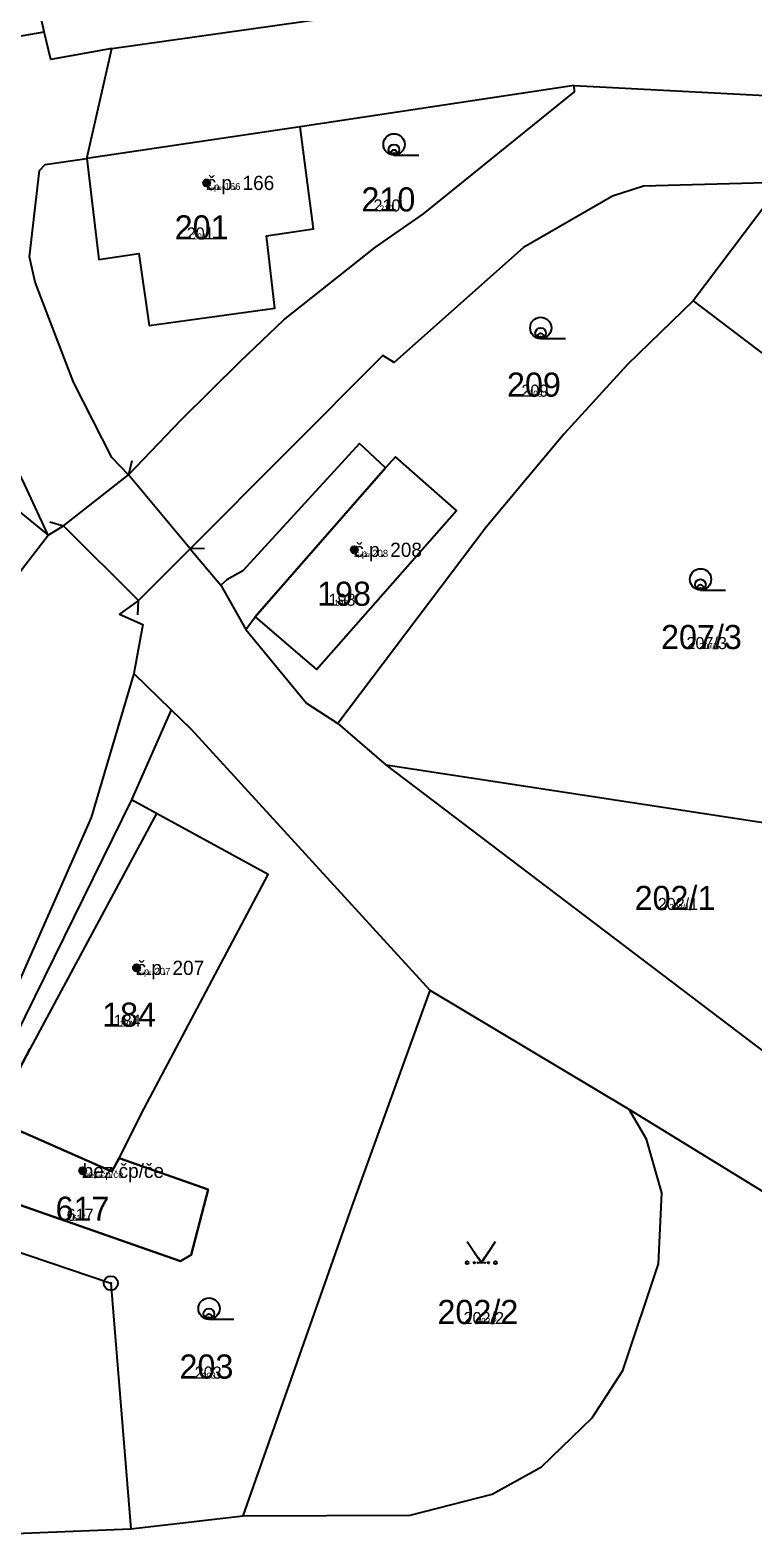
# Model space of a CAD drawing. Extents: x -744652 to -739090, y -980828 to -975855.
# Drawn here: x -742254.9 to -742204.1, y -978789.8 to -978683.6 of the extents above; entities that cross this region are included whole.
import ezdxf

# ---------------------------------------------------------------- set-up
doc = ezdxf.new("R2010")
doc.units = 0
for name, color, linetype in [('KAT_02_hranice parcel', 7, 'Continuous'), ('KAT_03_1000_st čísla parcelní', 7, 'Continuous'), ('KAT_03_1000_čísla parcelní', 7, 'Continuous'), ('KAT_03_1000_čísla popisná', 7, 'Continuous'), ('KAT_03_100_st čísla parcelní', 7, 'Continuous'), ('KAT_03_100_čísla parcelní', 7, 'Continuous'), ('KAT_03_100_čísla popisná', 7, 'Continuous'), ('KAT_03_250_st čísla parcelní', 7, 'Continuous'), ('KAT_03_250_čísla parcelní', 7, 'Continuous'), ('KAT_03_250_čísla popisná', 7, 'Continuous'), ('KAT_03_500_st čísla parcelní', 7, 'Continuous'), ('KAT_03_500_čísla parcelní', 7, 'Continuous'), ('KAT_03_500_čísla popisná', 7, 'Continuous'), ('KAT_04_vnitřní kresba', 7, 'Continuous'), ('KAT_05_1000_značky kultur', 7, 'Continuous'), ('KAT_05_100_značky kultur', 7, 'Continuous'), ('KAT_05_250_značky kultur', 7, 'Continuous'), ('KAT_05_500_značky kultur', 7, 'Continuous'), ('KAT_07_1000_značky budov', 7, 'Continuous'), ('KAT_07_100_značky budov', 7, 'Continuous'), ('KAT_07_500_značky budov', 7, 'Continuous'), ('KAT_11_značky bodu BP', 7, 'Continuous'), ('KAT_14_plocha_budovy', 7, 'Continuous')]:
    doc.layers.add(name, color=color, linetype=linetype)

msp = doc.modelspace()

# ---------------------------------------------------------------- linework, layer by layer
at = {"layer": 'KAT_02_hranice parcel'}
for p, q in [((-742253.92, -978683.75), (-742256.12, -978674.23)), ((-742249.16, -978684.92), (-742229.9, -978682.2)), ((-742250.94, -978692.66), (-742249.16, -978684.92)), ((-742216.65, -978687.54), (-742235.91, -978690.44)), ((-742235.91, -978690.44), (-742250.94, -978692.66)), ((-742243.66, -978720.15), (-742241.49, -978722.71)), ((-742241.49, -978722.71), (-742239.75, -978725.82)), ((-742245, -978731.48), (-742247.62, -978728.93)), ((-742245, -978731.48), (-742247.78, -978737.83)), ((-742233.28, -978732.45), (-742229.86, -978735.38)), ((-742229.86, -978735.38), (-742202.46, -978756.19)), ((-742200.11, -978739.93), (-742229.86, -978735.38)), ((-742247.78, -978737.83), (-742260.24, -978763.13)), ((-742212.78, -978759.62), (-742226.77, -978751.25)), ((-742198.03, -978768.69), (-742212.78, -978759.62)), ((-742247.84, -978789.14), (-742239.93, -978788.24))]:
    msp.add_line(p, q, dxfattribs=at)
for points in [[(-742295.99, -978688.82), (-742287.76, -978689.58), (-742287.82, -978690.14), (-742286.97, -978690.21), (-742286.81, -978689.69), (-742265.35, -978685.74), (-742253.92, -978683.75)], [(-742249.16, -978684.92), (-742253.45, -978685.69), (-742253.92, -978683.75)], [(-742248, -978714.93), (-742244.3, -978711.07), (-742240.12, -978706.95), (-742237.06, -978704.04), (-742230.63, -978698.92), (-742227.24, -978696.57), (-742216.61, -978687.98), (-742216.65, -978687.54)], [(-742216.65, -978687.54), (-742202.73, -978688.25), (-742196.45, -978690.11), (-742194.34, -978691.41), (-742192.8, -978692.35), (-742189.04, -978695.18), (-742173.16, -978709.75), (-742166.45, -978714.63), (-742161.92, -978717.51), (-742156.4, -978720.68), (-742110.16, -978740.68), (-742085.64, -978751.42), (-742066.41, -978761.84), (-742062.23, -978766.39), (-742061.65, -978767.53), (-742052.39, -978779.37), (-742045.8, -978788.93)], [(-742250.94, -978692.66), (-742250.09, -978699.79), (-742247.26, -978699.36), (-742246.54, -978704.43), (-742237.7, -978703.2), (-742238.28, -978698.11), (-742234.98, -978697.63), (-742235.91, -978690.44)], [(-742248, -978714.93), (-742249.18, -978713.71), (-742251.87, -978708.42), (-742254.57, -978701.37), (-742254.97, -978699.59), (-742254.26, -978693.51), (-742253.85, -978693.09), (-742250.94, -978692.66)], [(-742202.27, -978694.37), (-742211.76, -978694.63), (-742213.94, -978695.32), (-742220.2, -978698.93), (-742229.3, -978707.04), (-742230.11, -978706.53), (-742243.66, -978720.15)], [(-742202.27, -978694.37), (-742202.84, -978695.52), (-742208.28, -978702.7)], [(-742253.66, -978719.18), (-742255.46, -978715.29), (-742261.65, -978703.21), (-742265.29, -978698.76), (-742268.77, -978697.28), (-742274.49, -978696.87), (-742278.62, -978699.47)], [(-742208.28, -978702.7), (-742212.9, -978707.18), (-742217.35, -978712.05), (-742222.84, -978718.63), (-742233.28, -978732.45)], [(-742208.28, -978702.7), (-742201.85, -978707.57), (-742199.68, -978709.84)], [(-742279.4, -978730.44), (-742277.71, -978707.74), (-742276.98, -978703.66), (-742268.28, -978707.22), (-742253.66, -978719.18)], [(-742239.75, -978725.82), (-742239.09, -978724.94), (-742234.78, -978728.65), (-742224.92, -978717.45), (-742229.22, -978713.67), (-742229.91, -978714.46), (-742231.74, -978712.74), (-742239.95, -978721.7), (-742241.09, -978722.33), (-742241.49, -978722.71)], [(-742253.66, -978719.18), (-742252.57, -978718.53), (-742248, -978714.93)], [(-742262.83, -978733.44), (-742258.16, -978725), (-742253.66, -978719.18)], [(-742243.66, -978720.15), (-742247.3, -978723.8), (-742248.63, -978724.76), (-742246.99, -978725.49), (-742247.62, -978728.93)], [(-742239.75, -978725.82), (-742235.47, -978731.02), (-742233.28, -978732.45)], [(-742247.62, -978728.93), (-742250.63, -978739.07), (-742262.99, -978767.12)], [(-742226.77, -978751.25), (-742243.57, -978732.88), (-742245, -978731.48)], [(-742248.65, -978763.05), (-742246.89, -978759.56), (-742238.17, -978743.09), (-742246.03, -978738.79), (-742247.78, -978737.83)], [(-742239.93, -978788.24), (-742232.26, -978766.43), (-742226.77, -978751.25)], [(-742239.93, -978788.24), (-742228.19, -978788.19), (-742222.41, -978786.71), (-742218.94, -978784.79), (-742215.38, -978781.34), (-742213.21, -978778.01), (-742210.71, -978770.48), (-742210.48, -978765.5), (-742211.54, -978761.72), (-742212.78, -978759.62)], [(-742257.54, -978760.3), (-742249.17, -978764), (-742248.65, -978763.05)], [(-742248.65, -978763.05), (-742242.4, -978765.25), (-742243.58, -978769.85), (-742244.33, -978770.31), (-742259.91, -978764.86)], [(-742262.35, -978767.41), (-742269.82, -978775.08), (-742287.73, -978785.83), (-742275.64, -978787.82), (-742263.54, -978789.78), (-742247.84, -978789.14)], [(-742262.35, -978767.41), (-742249.24, -978771.85), (-742247.84, -978789.14)]]:
    msp.add_lwpolyline(points, dxfattribs=at)
at = {"layer": 'KAT_03_1000_čísla popisná'}
for centre in [(-742242.5, -978694.39), (-742242.5, -978694.39), (-742232.11, -978720.22), (-742232.11, -978720.22), (-742247.43, -978749.65), (-742247.43, -978749.65), (-742251.22, -978763.94), (-742251.22, -978763.94)]:
    msp.add_circle(centre, 0.25, dxfattribs=at)
at = {"layer": 'KAT_03_100_čísla popisná'}
for centre in [(-742242.5, -978694.39), (-742242.5, -978694.39), (-742232.11, -978720.22), (-742232.11, -978720.22), (-742247.43, -978749.65), (-742247.43, -978749.65), (-742251.22, -978763.94), (-742251.22, -978763.94)]:
    msp.add_circle(centre, 0.025, dxfattribs=at)
at = {"layer": 'KAT_03_250_čísla popisná'}
for centre in [(-742242.5, -978694.39), (-742242.5, -978694.39), (-742232.11, -978720.22), (-742232.11, -978720.22), (-742247.43, -978749.65), (-742247.43, -978749.65), (-742251.22, -978763.94), (-742251.22, -978763.94)]:
    msp.add_circle(centre, 0.0625, dxfattribs=at)
at = {"layer": 'KAT_03_500_čísla popisná'}
for centre in [(-742242.5, -978694.39), (-742242.5, -978694.39), (-742232.11, -978720.22), (-742232.11, -978720.22), (-742247.43, -978749.65), (-742247.43, -978749.65), (-742251.22, -978763.94), (-742251.22, -978763.94)]:
    msp.add_circle(centre, 0.125, dxfattribs=at)
at = {"layer": 'KAT_04_vnitřní kresba'}
for p, q in [((-742247.77, -978713.96), (-742248, -978714.93)), ((-742243.66, -978720.15), (-742248, -978714.93)), ((-742239.09, -978724.94), (-742229.91, -978714.46)), ((-742253.53, -978718.24), (-742252.57, -978718.53)), ((-742252.57, -978718.53), (-742247.3, -978723.8)), ((-742242.66, -978720.12), (-742243.66, -978720.15)), ((-742247.35, -978724.8), (-742247.3, -978723.8)), ((-742246.03, -978738.79), (-742254.91, -978755.34)), ((-742257.54, -978760.3), (-742254.91, -978755.34))]:
    msp.add_line(p, q, dxfattribs=at)
at = {"layer": 'KAT_05_1000_značky kultur'}
for p, q in [((-742229.31, -978692.43), (-742227.56, -978692.43)), ((-742218.99, -978705.35), (-742217.24, -978705.35)), ((-742207.75, -978723.05), (-742206, -978723.05)), ((-742242.33, -978774.39), (-742240.58, -978774.39))]:
    msp.add_line(p, q, dxfattribs=at)
msp.add_lwpolyline([(-742224.17, -978768.91), (-742223.17, -978770.41), (-742222.17, -978768.91)], dxfattribs=at)
for centre, radius in [((-742229.31, -978691.68), 0.75), ((-742218.99, -978704.6), 0.75), ((-742207.75, -978722.3), 0.75), ((-742224.17, -978770.41), 0.1), ((-742222.17, -978770.41), 0.1), ((-742242.33, -978773.64), 0.75)]:
    msp.add_circle(centre, radius, dxfattribs=at)
at = {"layer": 'KAT_05_100_značky kultur'}
for p, q in [((-742229.32, -978692.43), (-742229.14, -978692.43)), ((-742219, -978705.35), (-742218.82, -978705.35)), ((-742207.76, -978723.05), (-742207.58, -978723.05)), ((-742242.34, -978774.39), (-742242.16, -978774.39))]:
    msp.add_line(p, q, dxfattribs=at)
msp.add_lwpolyline([(-742223.27, -978770.26), (-742223.17, -978770.41), (-742223.07, -978770.26)], dxfattribs=at)
for centre, radius in [((-742229.32, -978692.35), 0.075), ((-742219, -978705.27), 0.075), ((-742207.76, -978722.97), 0.075), ((-742223.27, -978770.41), 0.01), ((-742223.07, -978770.41), 0.01), ((-742242.34, -978774.31), 0.075)]:
    msp.add_circle(centre, radius, dxfattribs=at)
at = {"layer": 'KAT_05_250_značky kultur'}
for p, q in [((-742229.32, -978692.43), (-742228.88, -978692.43)), ((-742219, -978705.35), (-742218.56, -978705.35)), ((-742207.76, -978723.05), (-742207.32, -978723.05)), ((-742242.34, -978774.39), (-742241.9, -978774.39))]:
    msp.add_line(p, q, dxfattribs=at)
msp.add_lwpolyline([(-742223.42, -978770.03), (-742223.17, -978770.41), (-742222.92, -978770.03)], dxfattribs=at)
for centre, radius in [((-742229.32, -978692.24), 0.187), ((-742219, -978705.16), 0.187), ((-742207.76, -978722.86), 0.187), ((-742223.42, -978770.41), 0.025), ((-742222.92, -978770.41), 0.025), ((-742242.34, -978774.2), 0.187)]:
    msp.add_circle(centre, radius, dxfattribs=at)
at = {"layer": 'KAT_05_500_značky kultur'}
for p, q in [((-742229.32, -978692.43), (-742228.44, -978692.43)), ((-742219, -978705.35), (-742218.12, -978705.35)), ((-742207.76, -978723.05), (-742206.88, -978723.05)), ((-742242.34, -978774.39), (-742241.46, -978774.39))]:
    msp.add_line(p, q, dxfattribs=at)
msp.add_lwpolyline([(-742223.67, -978769.66), (-742223.17, -978770.41), (-742222.67, -978769.66)], dxfattribs=at)
for centre, radius in [((-742229.32, -978692.05), 0.375), ((-742219, -978704.97), 0.375), ((-742207.76, -978722.67), 0.375), ((-742223.67, -978770.41), 0.05), ((-742222.67, -978770.41), 0.05), ((-742242.34, -978774.01), 0.375)]:
    msp.add_circle(centre, radius, dxfattribs=at)
at = {"layer": 'KAT_07_1000_značky budov'}
for centre in [(-742242.51, -978694.39), (-742232.12, -978720.22), (-742247.44, -978749.65), (-742251.23, -978763.94)]:
    msp.add_circle(centre, 0.175, dxfattribs=at)
at = {"layer": 'KAT_07_100_značky budov'}
for centre in [(-742242.5, -978694.39), (-742232.11, -978720.22), (-742247.43, -978749.65), (-742251.22, -978763.94)]:
    msp.add_circle(centre, 0.0175, dxfattribs=at)
at = {"layer": 'KAT_07_500_značky budov'}
for centre, radius in [((-742242.5, -978694.39), 0.0875), ((-742242.5, -978694.39), 0.0438), ((-742232.11, -978720.22), 0.0875), ((-742232.11, -978720.22), 0.0438), ((-742247.43, -978749.65), 0.0875), ((-742247.43, -978749.65), 0.0438), ((-742251.22, -978763.94), 0.0875), ((-742251.22, -978763.94), 0.0438)]:
    msp.add_circle(centre, radius, dxfattribs=at)
at = {"layer": 'KAT_11_značky bodu BP'}
for radius in [0.5, 0.0303]:
    msp.add_circle((-742249.24, -978771.85), radius, dxfattribs=at)
at = {"layer": 'KAT_14_plocha_budovy'}
for points in [[(-742250.94, -978692.66), (-742250.09, -978699.79), (-742247.26, -978699.36), (-742246.54, -978704.43), (-742237.7, -978703.2), (-742238.28, -978698.11), (-742234.98, -978697.63), (-742235.91, -978690.44)], [(-742202.84, -978695.52), (-742208.28, -978702.7), (-742201.85, -978707.57), (-742200.15, -978705.34), (-742197.6, -978707.28), (-742195.17, -978704.29), (-742193.67, -978702.45), (-742196.39, -978700.4)], [(-742239.09, -978724.94), (-742234.78, -978728.65), (-742224.92, -978717.45), (-742229.22, -978713.67), (-742229.91, -978714.46)], [(-742257.54, -978760.3), (-742249.17, -978764), (-742248.65, -978763.05), (-742246.89, -978759.56), (-742238.17, -978743.09), (-742246.03, -978738.79), (-742254.91, -978755.34)], [(-742259.91, -978764.86), (-742244.33, -978770.31), (-742243.58, -978769.85), (-742242.4, -978765.25), (-742248.65, -978763.05), (-742249.17, -978764), (-742257.54, -978760.3), (-742259.08, -978763.26)]]:
    msp.add_lwpolyline(points, close=True, dxfattribs=at)

# ---------------------------------------------------------------- texts
at = {"layer": 'KAT_03_1000_st čísla parcelní'}
for s, p in [('201', (-742244.75, -978698.37)), ('198', (-742234.73, -978724.16)), ('184', (-742249.85, -978753.8)), ('617', (-742253.13, -978767.46))]:
    msp.add_text(s, height=1.7, dxfattribs=at).set_placement(p)
at = {"layer": 'KAT_03_1000_čísla parcelní'}
for s, p in [('210', (-742231.61, -978696.4)), ('209', (-742221.37, -978709.44)), ('207/3', (-742210.53, -978727.21)), ('202/1', (-742212.39, -978745.58)), ('202/2', (-742226.26, -978774.73)), ('203', (-742244.41, -978778.57))]:
    msp.add_text(s, height=1.7, dxfattribs=at).set_placement(p)
at = {"layer": 'KAT_03_1000_čísla popisná'}
for s, height, p in [('č.p. 166', 1, (-742242.5, -978694.89)), ('201', 0.017, (-742243.06, -978698.37)), ('č.p. 208', 1, (-742232.11, -978720.72)), ('198', 0.017, (-742233.12, -978724.16)), ('č.p. 207', 1, (-742247.43, -978750.15)), ('184', 0.017, (-742248.24, -978753.8)), ('bez čp/če', 1, (-742251.22, -978764.44)), ('617', 0.017, (-742251.58, -978767.46))]:
    msp.add_text(s, height=height, dxfattribs=at).set_placement(p)
at = {"layer": 'KAT_03_100_st čísla parcelní'}
for s, p in [('201', (-742243.22, -978698.37)), ('198', (-742233.27, -978724.16)), ('184', (-742248.38, -978753.8)), ('617', (-742251.72, -978767.46))]:
    msp.add_text(s, height=0.17, dxfattribs=at).set_placement(p)
at = {"layer": 'KAT_03_100_čísla parcelní'}
for s, p in [('210', (-742230.08, -978696.4)), ('209', (-742219.52, -978709.44)), ('207/3', (-742207.31, -978727.21)), ('202/1', (-742209.46, -978745.58)), ('202/2', (-742222.95, -978774.73)), ('203', (-742242.49, -978778.57))]:
    msp.add_text(s, height=0.17, dxfattribs=at).set_placement(p)
at = {"layer": 'KAT_03_100_čísla popisná'}
for s, height, p in [('č.p. 166', 0.1, (-742242.5, -978694.89)), ('201', 0.0017, (-742243.05, -978698.37)), ('č.p. 208', 0.1, (-742232.11, -978720.72)), ('198', 0.0017, (-742233.11, -978724.16)), ('č.p. 207', 0.1, (-742247.43, -978750.15)), ('184', 0.0017, (-742248.22, -978753.8)), ('bez čp/če', 0.1, (-742251.22, -978764.44)), ('617', 0.0017, (-742251.57, -978767.46))]:
    msp.add_text(s, height=height, dxfattribs=at).set_placement(p)
at = {"layer": 'KAT_03_250_st čísla parcelní'}
for s, p in [('201', (-742243.47, -978698.37)), ('198', (-742233.51, -978724.16)), ('184', (-742248.63, -978753.8)), ('617', (-742251.96, -978767.46))]:
    msp.add_text(s, height=0.425, dxfattribs=at).set_placement(p)
at = {"layer": 'KAT_03_250_čísla parcelní'}
for s, p in [('210', (-742230.33, -978696.4)), ('209', (-742219.83, -978709.44)), ('207/3', (-742207.85, -978727.21)), ('202/1', (-742209.95, -978745.58)), ('202/2', (-742223.5, -978774.73)), ('203', (-742242.81, -978778.57))]:
    msp.add_text(s, height=0.425, dxfattribs=at).set_placement(p)
at = {"layer": 'KAT_03_250_čísla popisná'}
for s, height, p in [('č.p. 166', 0.25, (-742242.5, -978694.89)), ('201', 0.00425, (-742243.05, -978698.37)), ('č.p. 208', 0.25, (-742232.11, -978720.72)), ('198', 0.00425, (-742233.11, -978724.16)), ('č.p. 207', 0.25, (-742247.43, -978750.15)), ('184', 0.00425, (-742248.23, -978753.8)), ('bez čp/če', 0.25, (-742251.22, -978764.44)), ('617', 0.00425, (-742251.57, -978767.46))]:
    msp.add_text(s, height=height, dxfattribs=at).set_placement(p)
at = {"layer": 'KAT_03_500_st čísla parcelní'}
for s, p in [('201', (-742243.9, -978698.37)), ('198', (-742233.92, -978724.16)), ('184', (-742249.04, -978753.8)), ('617', (-742252.35, -978767.46))]:
    msp.add_text(s, height=0.85, dxfattribs=at).set_placement(p)
at = {"layer": 'KAT_03_500_čísla parcelní'}
for s, p in [('210', (-742230.76, -978696.4)), ('209', (-742220.35, -978709.44)), ('207/3', (-742208.74, -978727.21)), ('202/1', (-742210.76, -978745.58)), ('202/2', (-742224.42, -978774.73)), ('203', (-742243.34, -978778.57))]:
    msp.add_text(s, height=0.85, dxfattribs=at).set_placement(p)
at = {"layer": 'KAT_03_500_čísla popisná'}
for s, height, p in [('č.p. 166', 0.5, (-742242.5, -978694.89)), ('201', 0.0085, (-742243.06, -978698.37)), ('č.p. 208', 0.5, (-742232.11, -978720.72)), ('198', 0.0085, (-742233.12, -978724.16)), ('č.p. 207', 0.5, (-742247.43, -978750.15)), ('184', 0.0085, (-742248.23, -978753.8)), ('bez čp/če', 0.5, (-742251.22, -978764.44)), ('617', 0.0085, (-742251.58, -978767.46))]:
    msp.add_text(s, height=height, dxfattribs=at).set_placement(p)

doc.saveas('drawing.dxf')
